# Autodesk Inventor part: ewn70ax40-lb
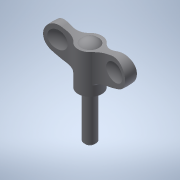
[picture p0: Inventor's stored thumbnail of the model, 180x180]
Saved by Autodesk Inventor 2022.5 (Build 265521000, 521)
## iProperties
Created: 2016-12
Part Number: ewn70ax40-lb
Material: 一般
Document SubType Name: Modeling
Designer: imaocorp
Density: 1 g/cm^3
Appearance: 既定
Author: imaocorp
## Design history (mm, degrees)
node "ewn70ax40-lb.x_t1"
node "ewn70ax40-lb"
node "Base1"
